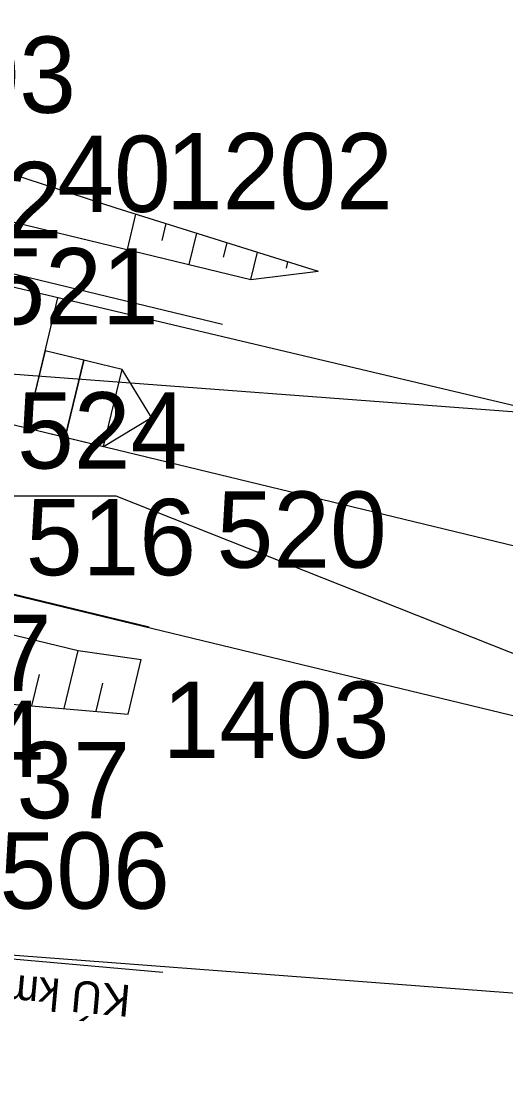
# Model space of a CAD drawing. Extents: x -748344 to -743169, y -1131966 to -1127091.
# Drawn here: x -747589.31 to -747581.68, y -1131717.22 to -1131700.6 of the extents above; entities that cross this region are included whole.
import ezdxf

# ---------------------------------------------------------------- set-up
doc = ezdxf.new("R2010")
doc.units = 0
for name, color, linetype in [('_Zabezpečovací zařízení', 7, 'Continuous'), ('_Zabezpečovací zařízení_trasa', 7, 'Continuous'), ('bublina_fialová_čára_tenká', 7, 'Continuous'), ('křížky', 7, 'Continuous'), ('OSA_KOLEJ', 7, 'Continuous'), ('POP_OBLOUKY', 7, 'Continuous'), ('SMEROVE_A_VYSKOVE_VYROVNANI', 7, 'Continuous'), ('SVAH', 7, 'Continuous'), ('TRATIVOD', 7, 'Continuous'), ('Vrstva 53', 7, 'Continuous'), ('Vrstva 60', 7, 'Continuous')]:
    doc.layers.add(name, color=color, linetype=linetype)

# ---------------------------------------------------------------- blocks, each defined once
blk = doc.blocks.new('POINT_DISPLAY')
blk.add_line((0, 0), (0, 0))

msp = doc.modelspace()

# ---------------------------------------------------------------- linework, layer by layer
at = {"layer": '_Zabezpečovací zařízení'}
for p, q in [((-747588.929, -1131705.783), (-747589.223, -1131706.998)), ((-747587.714, -1131706.077), (-747588.929, -1131705.783)), ((-747588.321, -1131705.93), (-747588.615, -1131707.145)), ((-747588.008, -1131707.292), (-747587.714, -1131706.077)), ((-747587.253, -1131706.832), (-747587.714, -1131706.077)), ((-747588.008, -1131707.292), (-747587.253, -1131706.832)), ((-747589.223, -1131706.998), (-747588.008, -1131707.292))]:
    msp.add_line(p, q, dxfattribs=at)
msp.add_lwpolyline([(-747589.223, -1131706.998), (-747588.615, -1131707.145), (-747588.321, -1131705.93), (-747588.929, -1131705.783), (-747589.223, -1131706.998)], dxfattribs=at)
at = {"layer": '_Zabezpečovací zařízení_trasa'}
msp.add_line((-747588.736, -1131704.951), (-747589.222, -1131706.998), dxfattribs=at)
msp.add_lwpolyline([(-747299.39, -1131774.358), (-747312.964, -1131771.536), (-747335.194, -1131765.862), (-747431.496, -1131743.033), (-747485.589, -1131729.823), (-747529.872, -1131718.897), (-747616.745, -1131698.315), (-747822.016, -1131648.41), (-747861.482, -1131639.038), (-748013.304, -1131601.999), (-748116.903, -1131577.077), (-748210.219, -1131554.485), (-748277.301, -1131538.228)], dxfattribs=at)
at = {"layer": 'bublina_fialová_čára_tenká'}
for p, q in [((-747518.052, -1131711.518), (-747594.166, -1131705.802)), ((-747545.254, -1131718.632), (-747593.043, -1131715.025))]:
    msp.add_line(p, q, dxfattribs=at)
at = {"layer": 'OSA_KOLEJ'}
msp.add_lwpolyline([(-747601.65, -1131703.991), (-747586.682, -1131707.613)], dxfattribs=at)
at = {"layer": 'POP_OBLOUKY'}
msp.add_line((-747592.99, -1131715.03), (-747587.076, -1131715.563), dxfattribs=at)
at = {"layer": 'SMEROVE_A_VYSKOVE_VYROVNANI'}
msp.add_lwpolyline([(-747586.682, -1131707.613), (-747539.653, -1131718.994)], dxfattribs=at)
at = {"layer": 'SVAH'}
for p, q in [((-747587.635, -1131704.193), (-747587.5, -1131703.634)), ((-747587.086, -1131704.047), (-747587.022, -1131703.784)), ((-747586.663, -1131704.428), (-747586.544, -1131703.934)), ((-747586.121, -1131704.314), (-747586.066, -1131704.084)), ((-747585.691, -1131704.663), (-747585.587, -1131704.233)), ((-747585.133, -1131704.483), (-747585.109, -1131704.383)), ((-747588.631, -1131711.413), (-747588.41, -1131710.499)), ((-747587.623, -1131711.5), (-747587.415, -1131710.64)), ((-747589.135, -1131711.37), (-747589.015, -1131710.876)), ((-747588.127, -1131711.457), (-747588.02, -1131711.013))]:
    msp.add_line(p, q, dxfattribs=at)
for points in [[(-747590.861, -1131702.545), (-747587.814, -1131703.536), (-747584.631, -1131704.533)], [(-747590.937, -1131703.394), (-747585.691, -1131704.663), (-747584.631, -1131704.533)], [(-747591.009, -1131704.189), (-747586.139, -1131705.367)], [(-747591.453, -1131709.119), (-747587.29, -1131710.126)], [(-747591.51, -1131709.749), (-747588.41, -1131710.499), (-747587.415, -1131710.64)], [(-747591.626, -1131711.037), (-747589.698, -1131711.322), (-747587.623, -1131711.5)]]:
    msp.add_lwpolyline(points, dxfattribs=at)
at = {"layer": 'TRATIVOD'}
msp.add_lwpolyline([(-747602.124, -1131706.551), (-747591.472, -1131709.129), (-747579.575, -1131712.008), (-747571.785, -1131715.287)], dxfattribs=at)
at = {"layer": 'Vrstva 53'}
msp.add_lwpolyline([(-747431.62, -1131748.34), (-747522.4, -1131724.74), (-747551.8, -1131720.33), (-747568.8, -1131715.62), (-747587.81, -1131708.07), (-747592.13, -1131708.07), (-747590.72, -1131696.79), (-747584.22, -1131698.64), (-747579.28, -1131700.12), (-747559.41, -1131702.48), (-747542.02, -1131707.68), (-747515.95, -1131716.72), (-747422.18, -1131737.69)], dxfattribs=at)
at = {"layer": 'Vrstva 60'}
for p, q in [((-747588.736, -1131704.951), (-747588.736, -1131704.951)), ((-747587.294, -1131710.14), (-747587.294, -1131710.14))]:
    msp.add_line(p, q, dxfattribs=at)

# ---------------------------------------------------------------- block references
at = {"layer": 'křížky', "xscale": 10, "yscale": 10, "rotation": 61.14491455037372}
for p in [(-747588.736, -1131704.951), (-747587.294, -1131710.14)]:
    msp.add_blockref('POINT_DISPLAY', p, dxfattribs=at)

# ---------------------------------------------------------------- texts
at = {"layer": 'POP_OBLOUKY'}
msp.add_text('KÚ km 0,018 155', height=0.5, rotation=174.8504, dxfattribs=at).set_placement((-747587.567, -1131715.769))
at = {"layer": 'Vrstva 60'}
for s, p in [('503', (-747591.12, -1131702.04)), ('1202', (-747587.028, -1131703.559)), ('40', (-747588.736, -1131703.599)), ('512', (-747591.331, -1131704.013)), ('521', (-747589.82, -1131705.37)), ('524', (-747589.369, -1131707.637)), ('520', (-747586.232, -1131709.198)), ('516', (-747589.232, -1131709.316)), ('517', (-747591.504, -1131711.136)), ('1403', (-747587.081, -1131712.19)), ('1404', (-747592.52, -1131712.489)), ('37', (-747589.378, -1131713.139)), ('506', (-747589.645, -1131714.562))]:
    msp.add_text(s, height=1.2, dxfattribs=at).set_placement(p)

doc.saveas('drawing.dxf')
